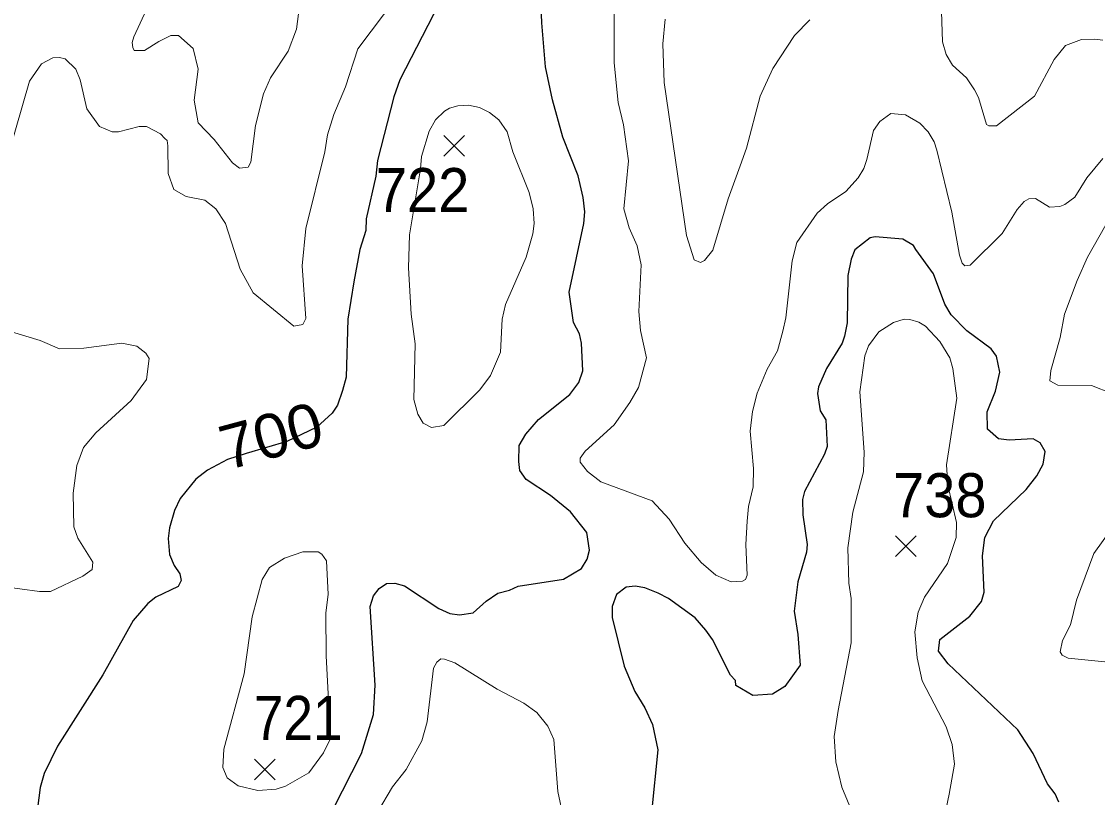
# Model space of a CAD drawing. Extents: x 294.2 to 320.3, y 7482.7 to 7510.7.
# Drawn here: x 303.742 to 305.694, y 7493.611 to 7495.019 of the extents above; entities that cross this region are included whole.
import ezdxf
from ezdxf.enums import TextEntityAlignment as Align

# ---------------------------------------------------------------- set-up
doc = ezdxf.new("R2010")
doc.units = 0
doc.header["$LTSCALE"] = 0.032
for name, color, linetype, lineweight in [('1', 7, 'Continuous', 25), ('2', 7, 'Continuous', 13), ('21', 7, 'Continuous', 25)]:
    doc.layers.add(name, color=color, linetype=linetype, lineweight=lineweight)
doc.layers.add('61', color=7, linetype='Continuous')

msp = doc.modelspace()

# ---------------------------------------------------------------- linework, layer by layer
at = {"layer": '1'}
for points in [[(304.53, 7495.1107), (304.4284, 7494.9128), (304.4176, 7494.8821), (304.388, 7494.7665), (304.3849, 7494.7378), (304.3678, 7494.6606), (304.3672, 7494.6395), (304.3563, 7494.605), (304.3454, 7494.5463), (304.3346, 7494.4786), (304.331, 7494.3733), (304.3249, 7494.3491), (304.3157, 7494.3227), (304.3059, 7494.3084), (304.278, 7494.2827), (304.2239, 7494.257), (304.1499, 7494.2351), (304.1159, 7494.2238), (304.08, 7494.2046), (304.0589, 7494.1887), (304.0301, 7494.1532), (304.0199, 7494.1313), (304.0108, 7494.1003), (304.0085, 7494.0807), (304.0108, 7494.052), (304.0191, 7494.0316), (304.0297, 7494.0165), (304.032, 7494.0044), (304.0267, 7493.9938), (303.986, 7493.9742), (303.9713, 7493.9627), (303.9451, 7493.9321), (303.8901, 7493.8337), (303.808, 7493.7038), (303.7838, 7493.6547), (303.7766, 7493.629), (303.7691, 7493.5731)], [(304.3751, 7493.9574), (304.3811, 7493.977), (304.3909, 7493.9898), (304.4045, 7493.9989), (304.4196, 7493.9997), (304.437, 7493.9951), (304.4996, 7493.9536), (304.5196, 7493.9445), (304.5369, 7493.9422), (304.5619, 7493.946), (304.5853, 7493.9672), (304.6065, 7493.9815), (304.6275, 7493.9868), (304.6432, 7493.9946), (304.7254, 7494.0067), (304.7579, 7494.0266), (304.7681, 7494.0432), (304.7726, 7494.0598), (304.7675, 7494.0917), (304.7381, 7494.1293), (304.7017, 7494.1587), (304.6576, 7494.1881), (304.6462, 7494.2041), (304.6442, 7494.2207), (304.6449, 7494.2494), (304.657, 7494.2698), (304.68, 7494.2966), (304.7369, 7494.3417), (304.7531, 7494.3636), (304.7607, 7494.3848), (304.7584, 7494.4354), (304.7546, 7494.452), (304.7433, 7494.4724), (304.736, 7494.5275), (304.7624, 7494.6521), (304.7639, 7494.6732), (304.7609, 7494.6996), (304.7518, 7494.7389), (304.7241, 7494.8088), (304.7058, 7494.8768), (304.6929, 7494.9365), (304.6864, 7495.0162), (304.6838, 7495.0756)], [(305.2814, 7494.6261), (305.254, 7494.6044), (305.247, 7494.5878), (305.2412, 7494.5578), (305.24, 7494.4722), (305.2349, 7494.448), (305.231, 7494.4352)], [(305.6241, 7493.6025), (305.6174, 7493.6176), (305.603, 7493.6357), (305.5773, 7493.6908), (305.5496, 7493.7335), (305.4232, 7493.8535), (305.4053, 7493.8765), (305.4079, 7493.8976), (305.4622, 7493.9397), (305.4838, 7493.9666), (305.4883, 7493.9832), (305.4851, 7494.0496), (305.4896, 7494.0828), (305.5055, 7494.1128), (305.5643, 7494.1696), (305.5841, 7494.1945), (305.5956, 7494.2156), (305.5988, 7494.2385), (305.5898, 7494.2545), (305.5771, 7494.2615), (305.5335, 7494.2592), (305.5146, 7494.2615), (305.4942, 7494.2789), (305.4941, 7494.3103), (305.5092, 7494.3481), (305.5169, 7494.3828), (305.5108, 7494.4115), (305.501, 7494.4251), (305.4572, 7494.4576), (305.4285, 7494.4863), (305.4168, 7494.5059), (305.3964, 7494.5611), (305.3647, 7494.6049), (305.36, 7494.612), (305.3408, 7494.6236), (305.291, 7494.628), (305.2814, 7494.6261)], [(305.231, 7494.4352), (305.2023, 7494.3892), (305.1882, 7494.356), (305.1863, 7494.3439), (305.1908, 7494.3126), (305.201, 7494.296), (305.2035, 7494.2475), (305.1991, 7494.2335), (305.1627, 7494.1658), (305.1589, 7494.1517), (305.1595, 7494.1236), (305.1672, 7494.07), (305.1659, 7494.056), (305.1506, 7494.0023), (305.1435, 7493.9487), (305.1506, 7493.9066), (305.1544, 7493.851), (305.1269, 7493.812), (305.1046, 7493.7986)], [(305.1046, 7493.7986), (305.0689, 7493.796), (305.0382, 7493.8139), (305.0375, 7493.8229), (305.0286, 7493.8331), (304.9954, 7493.8976), (304.9833, 7493.9142), (304.9641, 7493.9366), (304.9159, 7493.9721), (304.897, 7493.9819), (304.8729, 7493.991), (304.8556, 7493.994), (304.8389, 7493.9925), (304.8216, 7493.9789), (304.814, 7493.9577), (304.814, 7493.9373), (304.8352, 7493.8491), (304.8549, 7493.8031), (304.8728, 7493.7737), (304.8868, 7493.7431), (304.8965, 7493.6971), (304.885, 7493.5835)], [(304.1296, 7493.2821), (304.189, 7493.4092), (304.3071, 7493.5886), (304.3589, 7493.6907), (304.3808, 7493.7617), (304.3838, 7493.8146), (304.3751, 7493.9574)]]:
    msp.add_lwpolyline(points, dxfattribs=at)
at = {"layer": '2'}
for points in [[(304.8345, 7494.8311), (304.8249, 7494.8719), (304.8173, 7494.9434), (304.8166, 7495.2295), (304.8134, 7495.2703), (304.8064, 7495.301), (304.7503, 7495.3916)], [(305.4085, 7495.1101), (305.413, 7494.9817), (305.4194, 7494.9588), (305.4309, 7494.9396), (305.4564, 7494.9166), (305.4711, 7494.8949), (305.4781, 7494.8809), (305.4928, 7494.8317), (305.4966, 7494.8291), (305.5107, 7494.8291), (305.5796, 7494.8834), (305.6154, 7494.9498), (305.6358, 7494.9753), (305.6652, 7494.9862), (305.6882, 7494.9868), (305.7035, 7494.9849)], [(304.1379, 7494.7525), (304.1533, 7494.7544), (304.1584, 7494.7633), (304.1667, 7494.8298), (304.1813, 7494.8873), (304.1941, 7494.9166), (304.226, 7494.9651), (304.2413, 7495.0047), (304.249, 7495.066)], [(304.4234, 7495.0635), (304.3524, 7494.969), (304.3301, 7494.9), (304.309, 7494.8502), (304.2975, 7494.8132), (304.2924, 7494.7825), (304.2579, 7494.6434), (304.2516, 7494.5757)], [(303.9694, 7495.0405), (303.9464, 7494.9907), (303.9432, 7494.9805), (303.9445, 7494.9715), (303.947, 7494.9658), (303.9656, 7494.9658), (303.9917, 7494.9824), (304.0134, 7494.9932), (304.0275, 7494.9932), (304.0537, 7494.9696)], [(304.9099, 7495.0226), (304.9054, 7494.9779), (304.9079, 7494.9077), (304.9488, 7494.6306), (304.9622, 7494.5865), (304.9737, 7494.5814), (304.9814, 7494.5852), (304.996, 7494.6038), (305.0241, 7494.697), (305.0458, 7494.757), (305.0573, 7494.7889), (305.0823, 7494.8834), (305.1052, 7494.9332), (305.1442, 7494.9932), (305.1723, 7495.0219)], [(304.0537, 7494.9696), (304.0626, 7494.9319), (304.0556, 7494.8758), (304.0626, 7494.8349), (304.092, 7494.8048), (304.1252, 7494.7621), (304.1379, 7494.7525)], [(304.1124, 7494.6523), (304.0952, 7494.6791), (304.0747, 7494.6944), (304.0409, 7494.7014), (304.0185, 7494.7136), (304.0083, 7494.743), (304.0077, 7494.7928), (304.0064, 7494.803), (304.0026, 7494.8062), (303.9943, 7494.8151), (303.9694, 7494.8279), (303.956, 7494.8279), (303.9183, 7494.8182), (303.9068, 7494.8182), (303.8838, 7494.8279), (303.8608, 7494.8604), (303.8487, 7494.9128), (303.8411, 7494.9319), (303.8219, 7494.9511), (303.8111, 7494.9536), (303.7995, 7494.953), (303.7785, 7494.9421), (303.7568, 7494.9102), (303.7191, 7494.778)], [(305.7035, 7494.7704), (305.6748, 7494.7353), (305.6531, 7494.7001), (305.6345, 7494.6867), (305.6256, 7494.6829), (305.6071, 7494.6816), (305.5815, 7494.6976), (305.5694, 7494.697), (305.5611, 7494.6919), (305.5483, 7494.6778), (305.5209, 7494.6338), (305.4628, 7494.5769), (305.4532, 7494.5756), (305.4487, 7494.5801), (305.4436, 7494.5948), (305.4296, 7494.6727), (305.4028, 7494.7851), (305.3977, 7494.8004), (305.3868, 7494.8183), (305.3715, 7494.8342), (305.346, 7494.8496), (305.3191, 7494.8515), (305.2993, 7494.8374), (305.2878, 7494.8208), (305.2757, 7494.7685), (305.27, 7494.7519), (305.2598, 7494.7353), (305.2374, 7494.7104), (305.2042, 7494.688), (305.1857, 7494.6708), (305.1487, 7494.6178), (305.1403, 7494.5846), (305.1288, 7494.4812), (305.1231, 7494.4569), (305.1135, 7494.4212), (305.095, 7494.388), (305.0765, 7494.3445), (305.0682, 7494.3113), (305.0637, 7494.2756), (305.0701, 7494.2079), (305.0695, 7494.1747), (305.0612, 7494.139), (305.0586, 7494.1121), (305.056, 7494.07), (305.0586, 7494.0144), (305.0554, 7494.0061), (305.0503, 7494.0036), (305.0293, 7494.0023), (305.0018, 7494.0144), (304.975, 7494.0374), (304.9456, 7494.0726), (304.9169, 7494.116), (304.8862, 7494.1491), (304.793, 7494.1836), (304.7687, 7494.2022), (304.7554, 7494.2194), (304.7554, 7494.2264), (304.7649, 7494.2392), (304.8173, 7494.2871), (304.846, 7494.3273), (304.8613, 7494.3548), (304.876, 7494.4084), (304.8652, 7494.4582), (304.8619, 7494.4927), (304.8664, 7494.577), (304.8588, 7494.6114), (304.8447, 7494.6446), (304.8351, 7494.6791), (304.8435, 7494.7659), (304.8345, 7494.8311)], [(304.2516, 7494.5757), (304.2579, 7494.4799), (304.2529, 7494.469), (304.2363, 7494.4658), (304.1628, 7494.5265), (304.1392, 7494.5693), (304.1124, 7494.6523)], [(305.7201, 7494.3439), (305.6831, 7494.3585), (305.6218, 7494.3592), (305.6077, 7494.3669), (305.609, 7494.3854), (305.6262, 7494.4454), (305.6339, 7494.4876), (305.6569, 7494.5489), (305.676, 7494.591), (305.7092, 7494.6497)], [(305.261, 7493.5554), (305.2304, 7493.6295), (305.2195, 7493.6754), (305.2163, 7493.7214), (305.2233, 7493.7686), (305.247, 7493.8912), (305.247, 7493.9717), (305.2431, 7493.9998), (305.2412, 7494.0636), (305.2501, 7494.1287), (305.2693, 7494.2015), (305.2706, 7494.2373), (305.2629, 7494.3471), (305.2718, 7494.4122), (305.2789, 7494.4301), (305.2974, 7494.4556), (305.3242, 7494.4729), (305.3434, 7494.4786), (305.3536, 7494.478), (305.3702, 7494.4735), (305.3817, 7494.4658), (305.4079, 7494.4384), (305.4264, 7494.4084), (305.4315, 7494.3892), (305.4391, 7494.3356), (305.42, 7494.2143), (305.4223, 7494.1778), (305.4385, 7494.1096), (305.4379, 7494.0828), (305.4219, 7494.0355), (305.3804, 7493.9742), (305.3689, 7493.9474), (305.3625, 7493.9117), (305.367, 7493.8644), (305.376, 7493.8223), (305.4194, 7493.7393), (305.4302, 7493.7073), (305.4347, 7493.6716), (305.4251, 7493.6167), (305.4136, 7493.5618)], [(303.7242, 7494.4556), (303.7766, 7494.4397), (303.8111, 7494.4249), (303.8558, 7494.4262), (303.9247, 7494.4352), (303.9515, 7494.4295), (303.9681, 7494.4167), (303.9739, 7494.4071), (303.9694, 7494.3694), (303.9413, 7494.3311), (303.8774, 7494.2724), (303.8551, 7494.2456), (303.843, 7494.213), (303.836, 7494.1632), (303.8372, 7494.1019), (303.8449, 7494.0815), (303.8717, 7494.0381)], [(305.6556, 7493.9691), (305.6875, 7494.0534), (305.7795, 7494.1824)], [(303.8717, 7494.0381), (303.8704, 7494.0247), (303.8538, 7494.0125), (303.7951, 7493.9844), (303.7753, 7493.9844), (303.7038, 7493.9946), (303.6744, 7493.9902)], [(305.7495, 7493.8529), (305.6409, 7493.8638), (305.63, 7493.8689), (305.6262, 7493.8753), (305.6307, 7493.8957), (305.6447, 7493.9244), (305.6556, 7493.9691)], [(304.3879, 7493.5843), (304.4155, 7493.63), (304.4402, 7493.662), (304.4686, 7493.7137), (304.4783, 7493.7482), (304.4898, 7493.8453), (304.4955, 7493.8567), (304.5032, 7493.8625), (304.5096, 7493.8618)], [(304.5096, 7493.8618), (304.5281, 7493.8554), (304.6053, 7493.8076), (304.6538, 7493.782), (304.6768, 7493.7654), (304.6972, 7493.7405), (304.7081, 7493.7163)], [(304.7081, 7493.7163), (304.7151, 7493.6218), (304.7253, 7493.5733)]]:
    msp.add_lwpolyline(points, dxfattribs=at)
for points in [[(304.6697, 7494.6337), (304.6576, 7494.591), (304.62, 7494.5054), (304.6142, 7494.4786), (304.6111, 7494.4186), (304.5932, 7494.3765), (304.574, 7494.3503), (304.5083, 7494.2858), (304.4859, 7494.2819), (304.4712, 7494.2902), (304.461, 7494.3062), (304.454, 7494.3331), (304.4566, 7494.4339), (304.4489, 7494.4876), (304.4444, 7494.5718), (304.4463, 7494.6319), (304.4664, 7494.7513), (304.4681, 7494.7739), (304.4821, 7494.8196), (304.4936, 7494.84), (304.5095, 7494.856), (304.5185, 7494.8617), (304.5338, 7494.8655), (304.553, 7494.8668), (304.5734, 7494.8629), (304.5913, 7494.8534), (304.6079, 7494.84), (304.6232, 7494.8183), (304.6334, 7494.7825), (304.6634, 7494.7085), (304.6704, 7494.6791), (304.6724, 7494.6523)], [(304.2943, 7493.9461), (304.295, 7493.8682), (304.302, 7493.7303), (304.3014, 7493.7156), (304.2899, 7493.692), (304.2637, 7493.6556), (304.221, 7493.6314), (304.2044, 7493.6263), (304.1712, 7493.6237), (304.1354, 7493.632), (304.1156, 7493.6467), (304.1079, 7493.6652), (304.1092, 7493.6984), (304.1463, 7493.835), (304.1609, 7493.9385), (304.1788, 7494.0062), (304.1922, 7494.0279), (304.2197, 7494.0451), (304.2529, 7494.0566), (304.2803, 7494.0566), (304.2874, 7494.0521), (304.2956, 7494.04), (304.2988, 7493.9793)]]:
    msp.add_lwpolyline(points, close=True, dxfattribs=at)
at = {"layer": '21'}
for p, q in [((304.5087, 7494.8117), (304.5462, 7494.7742)), ((304.5462, 7494.8117), (304.5087, 7494.7742)), ((305.3274, 7494.0854), (305.3649, 7494.0479)), ((305.3649, 7494.0854), (305.3274, 7494.0479)), ((304.1652, 7493.6806), (304.2027, 7493.6431)), ((304.2027, 7493.6806), (304.1652, 7493.6431))]:
    msp.add_line(p, q, dxfattribs=at)

# ---------------------------------------------------------------- texts
at = {"layer": '61'}
for s, width, p in [('722', 0.95, (304.4699, 7494.6728)), ('738', 0.95, (305.4079, 7494.1193)), ('721', 0.9, (304.2443, 7493.7153))]:
    msp.add_text(s, height=0.08, dxfattribs=dict(at, width=width)).set_placement(p, align=Align.CENTER)
at = {"layer": '61', "width": 1.05}
msp.add_text('700', height=0.08, rotation=15.048, dxfattribs=at).set_placement((304.2055, 7494.2286), align=Align.CENTER)

doc.saveas('drawing.dxf')
